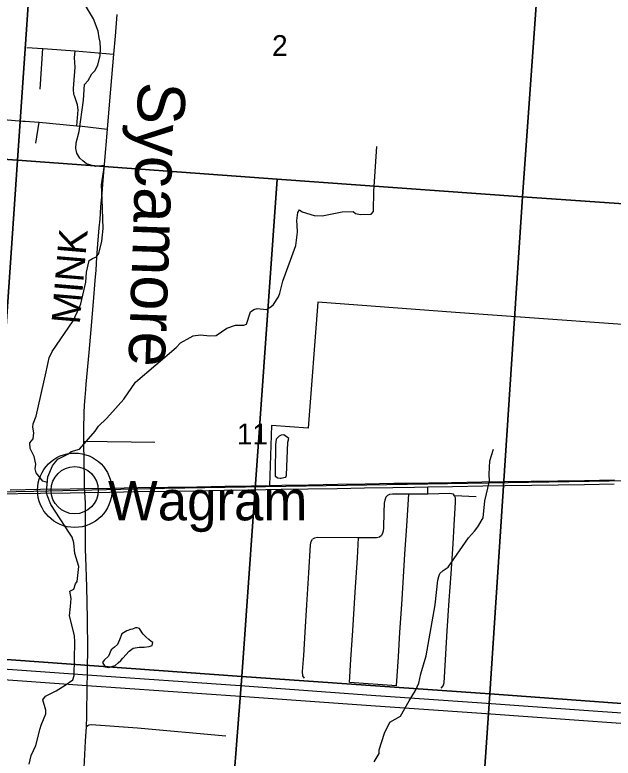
# Model space of a CAD drawing. Extents: x 0 to 34, y 0 to 22.
# Drawn here: x 6.46 to 7.657, y 18.88 to 20.367 of the extents above; entities that cross this region are included whole.
import ezdxf

# ---------------------------------------------------------------- set-up
doc = ezdxf.new("R2010")
doc.units = 0
for name, color, linetype in [('GM_X_Corporation', 7, 'Continuous'), ('GM_X_County_Road', 7, 'Continuous'), ('GM_X_County_Road_Text', 7, 'Continuous'), ('GM_X_Interstate_Route', 7, 'Continuous'), ('GM_X_Minor_Lake', 7, 'Continuous'), ('GM_X_Minor_River', 7, 'Continuous'), ('GM_X_Minor_River_Text', 7, 'Continuous'), ('GM_X_Rail_Line', 7, 'Continuous'), ('GM_X_Section_Text', 7, 'Continuous'), ('GM_X_Township_Road', 7, 'Continuous'), ('GM_X_Unincorporated', 7, 'Continuous'), ('GM_X_Unincorporated_Location', 7, 'Continuous'), ('GM_X_Unincorporated_Text', 7, 'Continuous'), ('GM_X_US_Route', 7, 'Continuous')]:
    doc.layers.add(name, color=color, linetype=linetype)

msp = doc.modelspace()

# ---------------------------------------------------------------- linework, layer by layer
at = {"layer": 'GM_X_Corporation'}
for points in [[(5.4919, 20.6855), (5.8824, 20.6656), (6.3999, 20.6351), (6.5029, 20.629), (6.4654, 20.076), (5.9674, 20.1102), (5.4537, 20.1473)], [(6.5029, 20.629), (6.929, 20.6031), (7.5154, 20.5644), (7.4756, 20.0027), (6.9844, 20.0383), (6.4654, 20.076)], [(7.5154, 20.5644), (7.7109, 20.5519), (7.7144, 20.5517), (8.2347, 20.5164), (8.5204, 20.4957), (8.4813, 19.9336), (7.9967, 19.9667), (7.4756, 20.0027)], [(5.9674, 20.1102), (6.4654, 20.076), (6.3967, 19.0805), (5.9022, 19.114)], [(6.4654, 20.076), (6.9844, 20.0383), (6.914, 19.0437), (6.3967, 19.0805)], [(6.9844, 20.0383), (7.4756, 20.0027), (7.41, 19.0084), (6.914, 19.0437)], [(7.4756, 20.0027), (7.9967, 19.9667), (7.9283, 18.9706), (7.41, 19.0084)], [(6.3967, 19.0805), (6.914, 19.0437), (6.8357, 18.0433), (6.3257, 18.0804)], [(6.914, 19.0437), (7.41, 19.0084), (7.3413, 18.0066), (6.8357, 18.0433)], [(7.41, 19.0084), (7.9283, 18.9706), (7.8463, 17.9699), (7.3413, 18.0066)]]:
    msp.add_lwpolyline(points, close=True, dxfattribs=at)
at = {"layer": 'GM_X_County_Road'}
for points in [[(6.6637, 20.3677), (6.6604, 20.3244), (6.6569, 20.2885), (6.6491, 20.1951), (6.6446, 20.1382), (6.6386, 20.0678), (6.6352, 20.0275), (6.6339, 20.0098), (6.6325, 19.996), (6.6315, 19.9836), (6.6302, 19.9697), (6.6296, 19.9584), (6.628, 19.9412), (6.6255, 19.9081), (6.6235, 19.8824), (6.6217, 19.8565), (6.6201, 19.8357), (6.6164, 19.7929), (6.6116, 19.7376), (6.6077, 19.6913), (6.602, 19.6279), (6.601, 19.6179), (6.6004, 19.609), (6.5999, 19.602), (6.5988, 19.5858), (6.598, 19.5717), (6.5976, 19.562), (6.5972, 19.5471), (6.597, 19.5315), (6.597, 19.5217), (6.597, 19.5144), (6.5979, 19.4709), (6.5982, 19.44), (6.5988, 19.4197), (6.5995, 19.4114)], [(6.5995, 19.4114), (6.6004, 19.3908), (6.6002, 19.363), (6.6007, 19.2988), (6.6021, 19.2629), (6.6032, 19.2227), (6.6043, 19.1596), (6.6052, 19.0952), (6.6046, 19.0628), (6.6043, 19.0467), (6.6039, 19.0257), (6.6034, 18.9641), (6.6022, 18.943), (6.6007, 18.9142), (6.5977, 18.8604)]]:
    msp.add_lwpolyline(points, dxfattribs=at)
at = {"layer": 'GM_X_Interstate_Route'}
for points in [[(6.2952, 19.0686), (6.6043, 19.0467), (6.911, 19.0252), (7.1726, 19.0063), (7.3941, 18.9908), (7.6264, 18.9743), (7.8582, 18.9579), (7.9538, 18.9505), (8.121, 18.9382), (8.4135, 18.9171), (8.6535, 18.9007), (8.825, 18.8902), (8.9, 18.885)], [(6.3995, 19.0399), (6.6039, 19.0257), (6.9106, 19.0042), (7.1722, 18.9854), (7.3938, 18.9698), (7.626, 18.9534), (7.8578, 18.937), (7.9472, 18.9307), (8.1146, 18.9188), (8.4071, 18.8978), (8.647, 18.8813), (8.8185, 18.8708), (8.9, 18.8652)]]:
    msp.add_lwpolyline(points, dxfattribs=at)
at = {"layer": 'GM_X_Minor_Lake'}
for points in [[(7.0059, 19.5123), (7.0081, 19.5198), (6.9979, 19.5267), (6.993, 19.5263), (6.9885, 19.5244), (6.9824, 19.5184), (6.9812, 19.5066), (6.9812, 19.4861), (6.9804, 19.4728), (6.9807, 19.444)], [(6.9807, 19.444), (6.986, 19.4409), (6.9909, 19.4398), (6.9925, 19.4398), (6.9981, 19.4413), (7.0019, 19.442), (7.0034, 19.4462), (7.0059, 19.5123)], [(6.7362, 19.1112), (6.7324, 19.1135), (6.7282, 19.1173), (6.7218, 19.1227), (6.7169, 19.128), (6.7143, 19.1306), (6.7093, 19.1394), (6.7044, 19.1409), (6.7014, 19.1405), (6.695, 19.1383), (6.6915, 19.1375), (6.6836, 19.1349), (6.6741, 19.1285), (6.6692, 19.1167), (6.665, 19.1076), (6.6589, 19.1019), (6.6525, 19.0966), (6.6471, 19.0841), (6.6384, 19.0758), (6.6354, 19.0712)], [(6.6354, 19.0712), (6.6403, 19.0625), (6.6478, 19.0617), (6.6539, 19.0632), (6.6607, 19.0651), (6.6668, 19.0704), (6.6721, 19.0753), (6.6759, 19.0799), (6.6888, 19.0939), (6.6968, 19.1003), (6.7085, 19.1022), (6.7187, 19.1018), (6.7286, 19.1037), (6.7347, 19.1055), (6.7362, 19.1112)]]:
    msp.add_lwpolyline(points, dxfattribs=at)
at = {"layer": 'GM_X_Minor_River'}
for points in [[(6.5248, 19.4315), (6.5161, 19.4344), (6.5025, 19.4511), (6.5002, 19.4587), (6.5021, 19.4682), (6.4984, 19.4838), (6.4904, 19.4998), (6.4901, 19.5111), (6.4965, 19.5187), (6.4981, 19.5305), (6.4955, 19.5419), (6.4966, 19.5487), (6.5027, 19.5643), (6.5222, 19.6527), (6.5283, 19.6807), (6.5344, 19.6932), (6.5762, 19.7546), (6.5891, 19.7823), (6.5921, 19.7888), (6.6021, 19.8324), (6.6033, 19.8525), (6.6082, 19.8753), (6.6154, 19.8798), (6.623, 19.8828), (6.6276, 19.8897), (6.6337, 19.9143), (6.6368, 19.9397), (6.6342, 19.9982), (6.6335, 20.027), (6.6389, 20.0657), (6.6211, 20.0635), (6.6029, 20.0692), (6.5961, 20.075), (6.5901, 20.0803), (6.5837, 20.0902), (6.5818, 20.0997), (6.5826, 20.1107), (6.5883, 20.1338), (6.5971, 20.1964), (6.5991, 20.2275), (6.6063, 20.2359), (6.6139, 20.2491), (6.62, 20.2552), (6.6257, 20.2666), (6.6306, 20.2859), (6.6314, 20.2996), (6.6303, 20.3121), (6.6284, 20.3208), (6.6262, 20.3345), (6.6175, 20.3592), (6.5994, 20.3888)], [(6.9723, 19.7826), (6.9776, 19.7875), (6.9871, 19.8027), (6.9898, 19.8099), (6.9963, 19.8342), (7.0218, 19.9055), (7.0256, 19.932), (7.0245, 19.9465), (7.0238, 19.9556), (7.0261, 19.9719), (7.0291, 19.9768), (7.0348, 19.9726), (7.059, 19.9657), (7.0749, 19.9646), (7.1151, 19.9728), (7.1367, 19.9739), (7.1416, 19.9693), (7.1518, 19.9674), (7.173, 19.9685), (7.1776, 19.9738), (7.1784, 20.0152), (7.1788, 20.0239), (7.1843, 20.1036)], [(6.4884, 18.8681), (6.4926, 18.8855), (6.5017, 18.9056), (6.5105, 18.9394), (6.5124, 18.9458), (6.5216, 18.969), (6.5219, 18.9758), (6.5156, 18.9967), (6.5209, 19.0039), (6.5425, 19.0149), (6.5607, 19.0262), (6.5755, 19.0368), (6.5785, 19.0452), (6.5798, 19.112), (6.5791, 19.1256), (6.5693, 19.1648), (6.5712, 19.1837), (6.5728, 19.1993), (6.5698, 19.2141), (6.5777, 19.2183), (6.5812, 19.2285), (6.5846, 19.2334), (6.588, 19.2634), (6.5801, 19.2896), (6.5775, 19.3109), (6.5745, 19.3223), (6.5689, 19.3303), (6.5319, 19.3873), (6.5243, 19.4059), (6.5228, 19.412), (6.5259, 19.4427), (6.5351, 19.4647), (6.5389, 19.47), (6.5461, 19.4784), (6.5669, 19.4886), (6.5726, 19.4935), (6.5889, 19.498), (6.6204, 19.5344), (6.6272, 19.5442), (6.6432, 19.5594), (6.65, 19.5666), (6.6781, 19.5984), (6.7013, 19.6321), (6.7828, 19.7014), (6.7912, 19.7109), (6.8105, 19.7218), (6.8169, 19.7249), (6.8313, 19.7271), (6.8499, 19.7248), (6.8624, 19.7255), (6.884, 19.7399), (6.9014, 19.7463), (6.9064, 19.7463), (6.9177, 19.7459), (6.9234, 19.7482), (6.9314, 19.7728), (6.9382, 19.7777), (6.9447, 19.7796), (6.9636, 19.7777), (6.9723, 19.7826)], [(7.1791, 18.8726), (7.1886, 18.8896), (7.189, 18.8969), (7.1997, 18.9302), (7.2103, 18.9519), (7.2312, 18.9643), (7.249, 18.995), (7.2616, 19.0151), (7.268, 19.0299), (7.2719, 19.0489), (7.2829, 19.0846), (7.2871, 19.1077), (7.3009, 19.1866), (7.306, 19.236), (7.3079, 19.2432), (7.3105, 19.2493), (7.317, 19.2557), (7.3272, 19.2621), (7.3679, 19.3209), (7.3796, 19.3341), (7.3865, 19.3425), (7.3967, 19.361), (7.4002, 19.3948), (7.4097, 19.4343), (7.409, 19.4483), (7.4106, 19.4745), (7.4178, 19.498)]]:
    msp.add_lwpolyline(points, dxfattribs=at)
at = {"layer": 'GM_X_Rail_Line'}
msp.add_lwpolyline([(3.8879, 19.3555), (4.0965, 19.3606), (5.5472, 19.3964), (6.4975, 19.4141), (6.7591, 19.4199), (8.4183, 19.4472), (8.6503, 19.4472), (8.9, 19.451)], dxfattribs=at)
at = {"layer": 'GM_X_Township_Road'}
for p, q in [((6.5103, 20.2183), (6.5155, 20.2999)), ((6.502, 20.1106), (6.5082, 20.152)), ((6.597, 19.5144), (6.7399, 19.512)), ((7.2861, 19.4084), (7.2865, 19.4226)), ((7.2237, 19.0247), (7.1295, 19.0315))]:
    msp.add_line(p, q, dxfattribs=at)
for points in [[(6.4841, 20.3016), (6.5155, 20.2999), (6.5807, 20.2947), (6.6569, 20.2885)], [(6.5839, 20.1447), (6.5863, 20.1772), (6.5854, 20.1872), (6.5819, 20.1971), (6.5789, 20.2047), (6.5779, 20.2079), (6.5775, 20.2108), (6.5771, 20.2147), (6.5772, 20.2198), (6.5779, 20.2286), (6.5802, 20.2625), (6.5789, 20.2812), (6.5807, 20.2947)], [(6.3316, 20.1653), (6.422, 20.1592), (6.4605, 20.1557), (6.4761, 20.1545)], [(6.4761, 20.1545), (6.4805, 20.1542), (6.5082, 20.152), (6.5839, 20.1447), (6.5943, 20.144), (6.6446, 20.1382)], [(7.8241, 19.7371), (7.3419, 19.7713), (7.0664, 19.792), (7.0468, 19.54), (6.9731, 19.5453), (6.9695, 19.4255)], [(7.383, 19.4027), (7.3397, 19.4049), (7.3373, 19.4078), (7.3339, 19.4088), (7.3302, 19.4092), (7.2861, 19.4084), (7.2483, 19.408), (7.2153, 19.4079), (7.2093, 19.4074), (7.2053, 19.4056), (7.2019, 19.4018), (7.1999, 19.3963), (7.1991, 19.3899), (7.1983, 19.3718), (7.1972, 19.3409), (7.1967, 19.3343), (7.1956, 19.3298), (7.1933, 19.3253), (7.1896, 19.3223), (7.1833, 19.3207), (7.1736, 19.3207), (7.1473, 19.3211), (7.0654, 19.3212), (7.0595, 19.3201), (7.0556, 19.3181)], [(7.2237, 19.0247), (7.2275, 19.0828), (7.2301, 19.1323), (7.234, 19.1875), (7.2368, 19.2317), (7.2401, 19.2879), (7.2439, 19.3448), (7.2483, 19.408)], [(7.3132, 19.0203), (7.3168, 19.0244), (7.3186, 19.0308), (7.3213, 19.0767), (7.325, 19.1345), (7.329, 19.1951), (7.3327, 19.2485), (7.3366, 19.3085), (7.3387, 19.3462), (7.3416, 19.3915), (7.3413, 19.4011), (7.3397, 19.4049)], [(7.0391, 19.0403), (7.0361, 19.0446), (7.0357, 19.0536), (7.038, 19.0857), (7.0409, 19.1319), (7.0441, 19.187), (7.048, 19.2508), (7.0517, 19.3071), (7.0528, 19.3136), (7.0556, 19.3181)], [(7.1295, 19.0315), (7.1322, 19.0774), (7.1362, 19.1355), (7.1407, 19.2118), (7.1453, 19.2806), (7.1473, 19.3211)], [(6.6022, 18.943), (6.6058, 18.9455), (6.6087, 18.9466), (6.6126, 18.9471), (6.7051, 18.9407), (6.8818, 18.9248)]]:
    msp.add_lwpolyline(points, dxfattribs=at)
at = {"layer": 'GM_X_Unincorporated'}
for radius in [0.0744, 0.0472]:
    msp.add_circle((6.5796, 19.416), radius, dxfattribs=at)
at = {"layer": 'GM_X_Unincorporated_Location'}
msp.add_line((6.5796, 19.416), (6.5796, 19.416), dxfattribs=at)
at = {"layer": 'GM_X_US_Route'}
for points in [[(6.4506, 19.417), (6.5109, 19.4181), (6.5705, 19.419), (6.5988, 19.4197), (6.6513, 19.4204), (6.7061, 19.4213), (6.7662, 19.4223), (6.8239, 19.4231), (6.8805, 19.4241), (6.9331, 19.425), (6.9695, 19.4255), (6.9938, 19.4258), (7.0474, 19.4269), (7.1061, 19.4278), (7.1611, 19.4287), (7.2181, 19.4298), (7.2614, 19.4304), (7.2881, 19.4307), (7.3337, 19.4315), (7.3942, 19.4325), (7.4403, 19.4332), (7.4931, 19.4339), (7.5464, 19.4348), (7.5997, 19.4357), (7.6595, 19.4368)], [(6.4204, 19.4086), (6.5111, 19.4101), (6.5707, 19.4109), (6.5995, 19.4114), (6.6497, 19.4123), (6.7045, 19.4132), (6.7646, 19.4142), (6.8221, 19.4151), (6.8789, 19.416), (6.9315, 19.4168), (6.993, 19.4179), (7.0458, 19.4188), (7.1045, 19.4197), (7.1597, 19.4208), (7.2165, 19.4217), (7.2598, 19.4223), (7.2865, 19.4226), (7.3353, 19.4234), (7.396, 19.4246), (7.4413, 19.4253), (7.4941, 19.4261), (7.547, 19.427), (7.5996, 19.4277), (7.6589, 19.4289)]]:
    msp.add_lwpolyline(points, dxfattribs=at)

# ---------------------------------------------------------------- texts
at = {"layer": 'GM_X_County_Road_Text'}
msp.add_text('MINK', height=0.05682, rotation=85.1744, dxfattribs=at).set_placement((6.5897, 19.7469))
at = {"layer": 'GM_X_Minor_River_Text'}
msp.add_text('Sycamore', height=0.09469, rotation=268.0002, dxfattribs=at).set_placement((6.707, 20.234))
at = {"layer": 'GM_X_Section_Text'}
for s, height, p in [('2', 0.0419, (6.9745, 20.2845)), ('11', 0.04186, (6.904, 19.5075))]:
    msp.add_text(s, height=height, rotation=0, dxfattribs=at).set_placement(p)
at = {"layer": 'GM_X_Unincorporated_Text'}
msp.add_text('Wagram', height=0.07898, rotation=0, dxfattribs=at).set_placement((6.6461, 19.3558))

doc.saveas('drawing.dxf')
